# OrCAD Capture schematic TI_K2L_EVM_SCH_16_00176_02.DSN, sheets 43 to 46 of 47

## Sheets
43 PAGE10 : K2L_FMC MARCONI CONN-1: size C; title: FMC Interface to JESD/RF devices-1
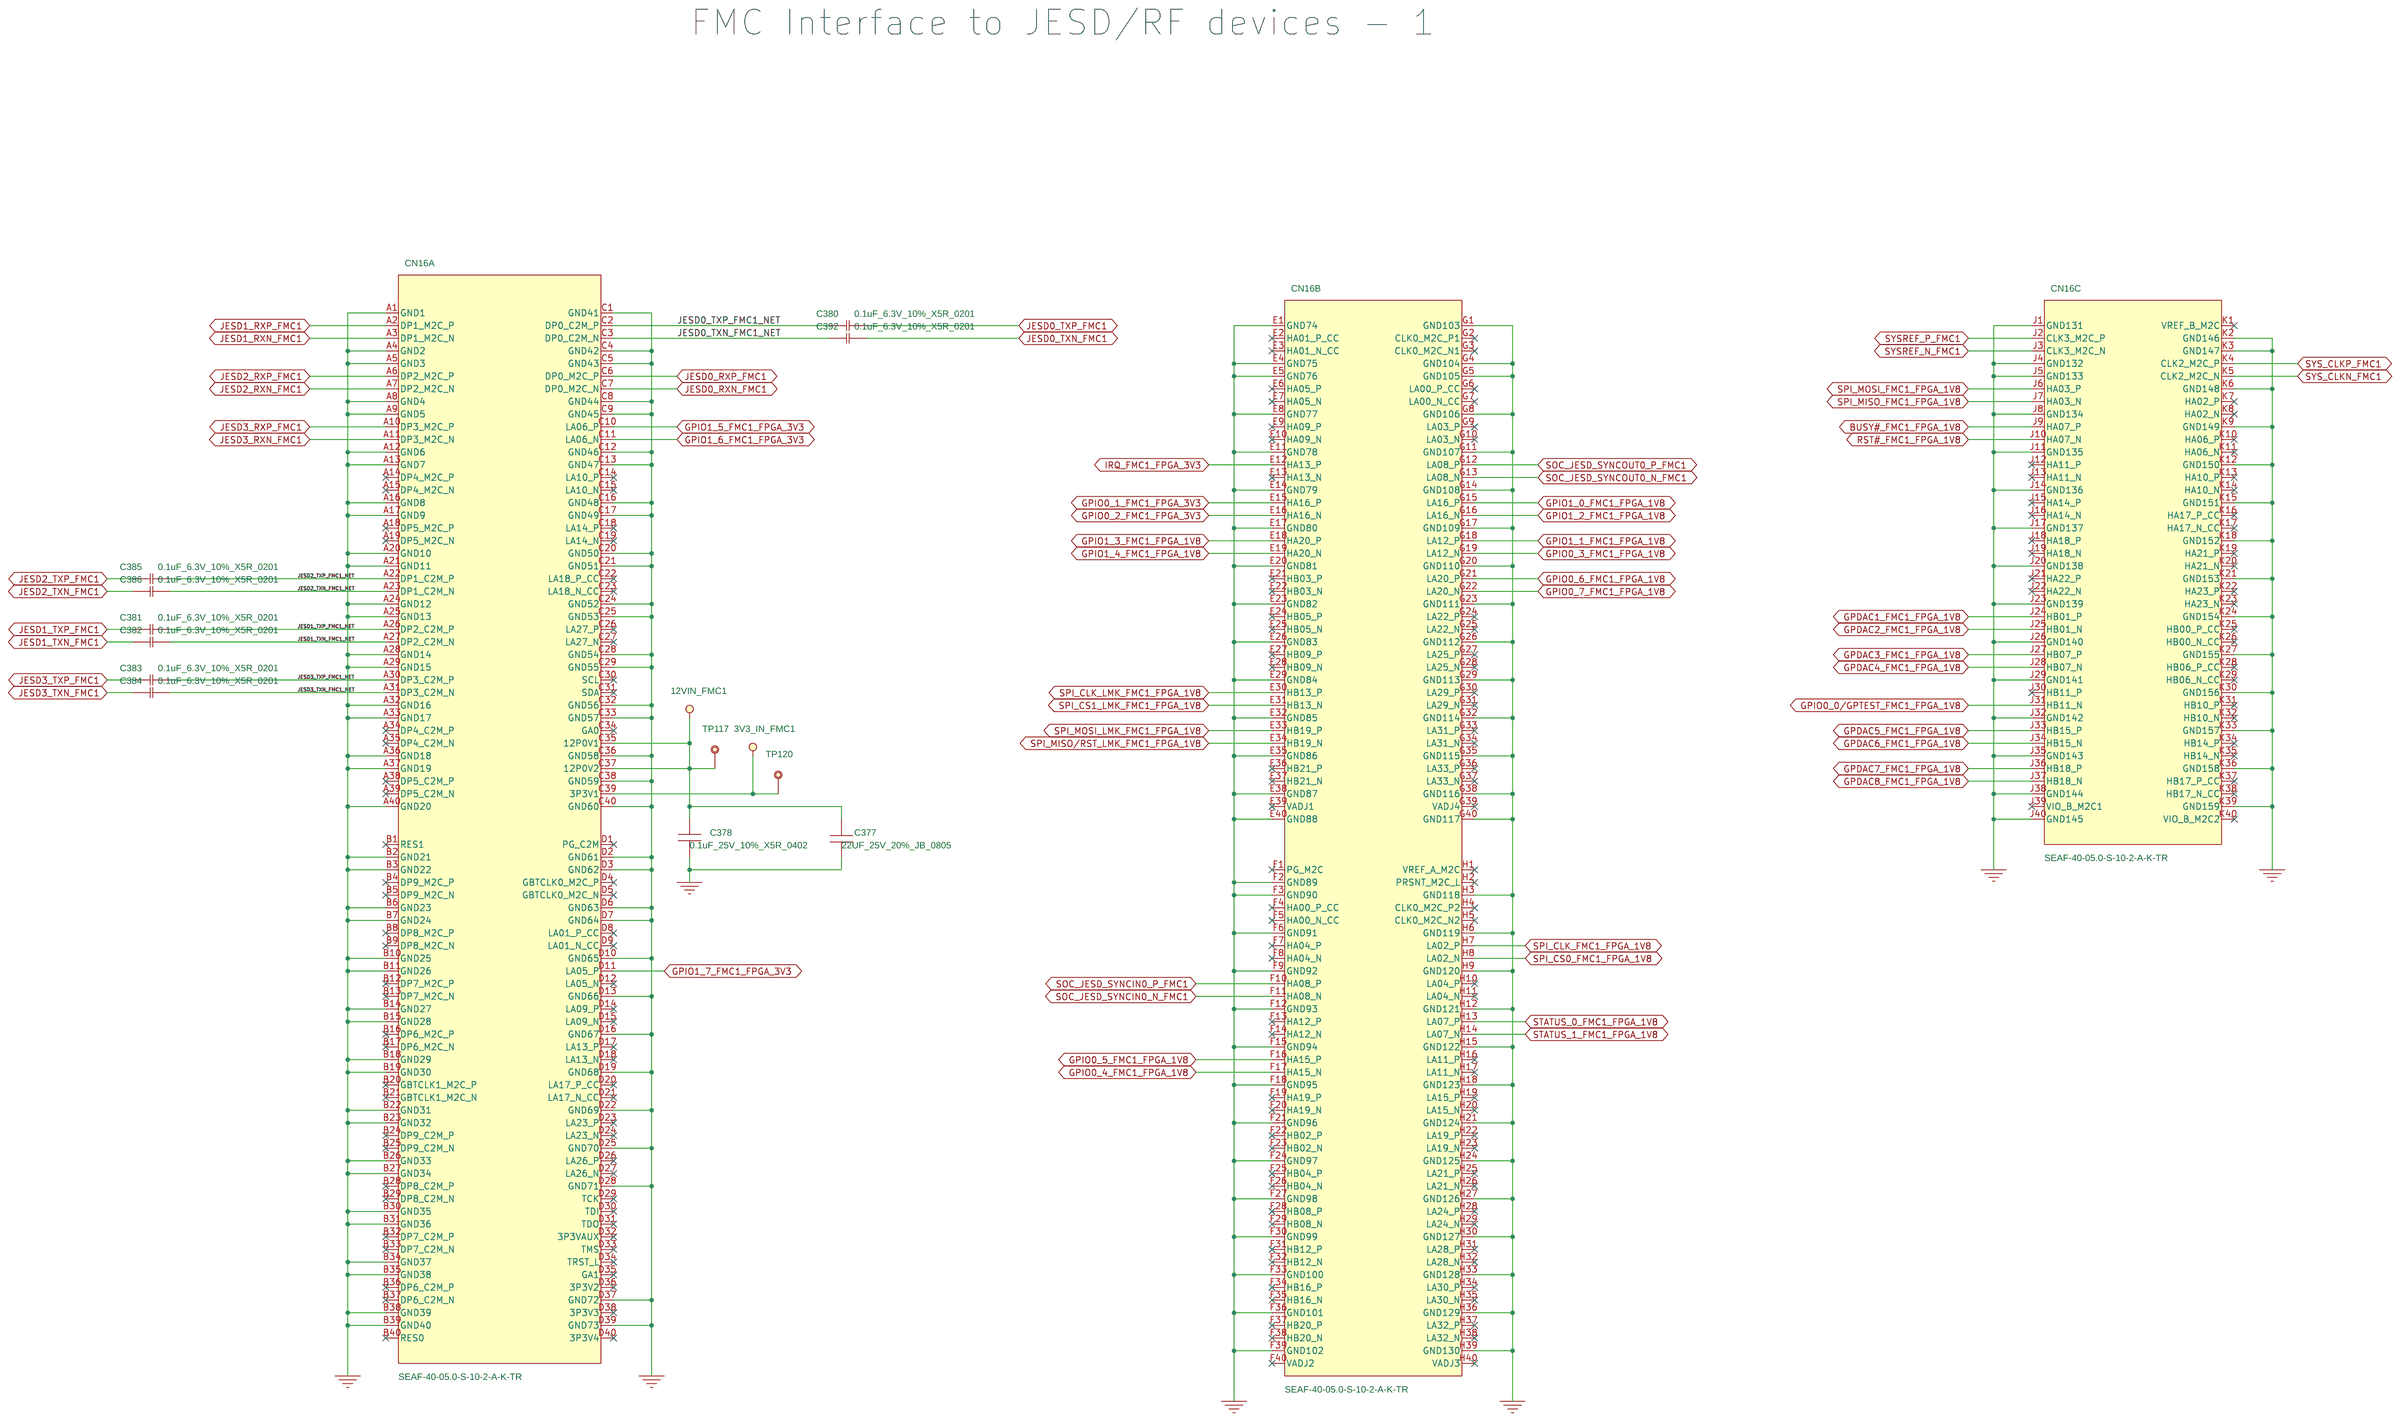
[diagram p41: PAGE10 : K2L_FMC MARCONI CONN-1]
44 PAGE03 : SYSTEM BLOCK DIAGRAM_C: title: BLOCK DIAGRAM
45 PAGE12 : K2L_SOC&FMC SERDES SW1: size C; title: JESD Serdes switch - 1
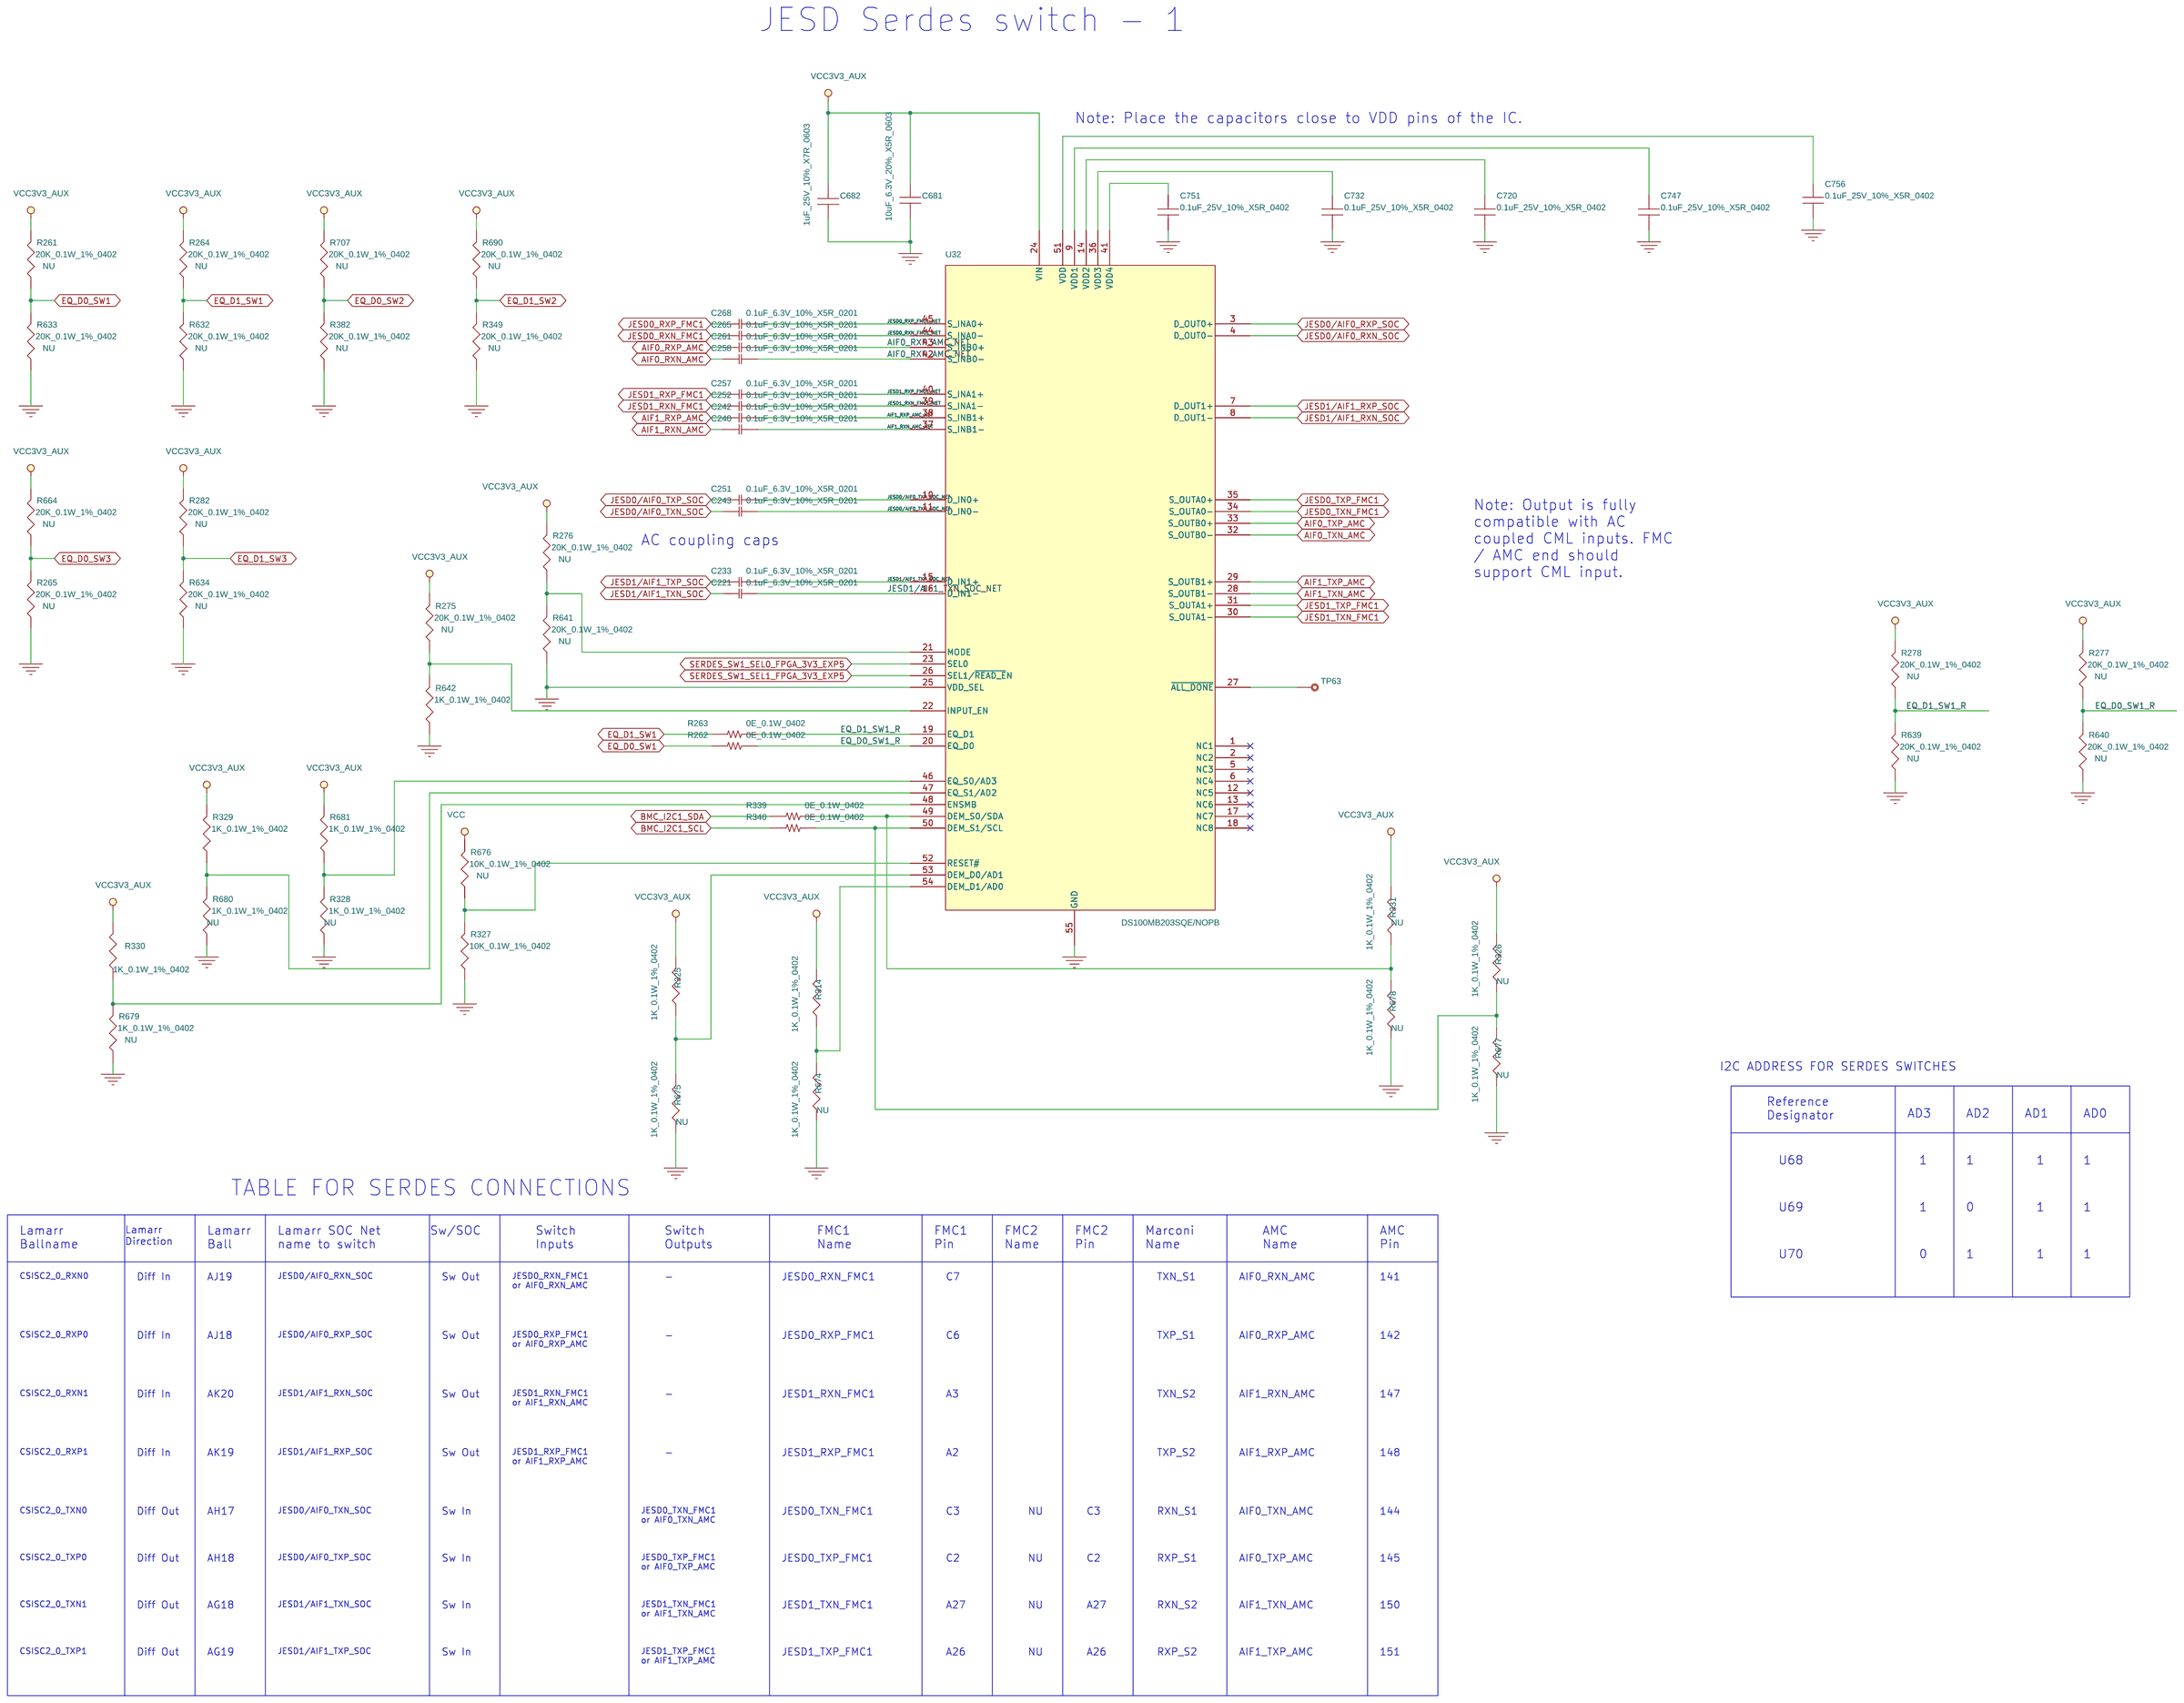
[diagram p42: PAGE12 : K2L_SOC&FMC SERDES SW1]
46 PAGE11 : K2L_FMC MARCONI CONN-2: size C; title: FMC Interface to JESD/RF devices - 2
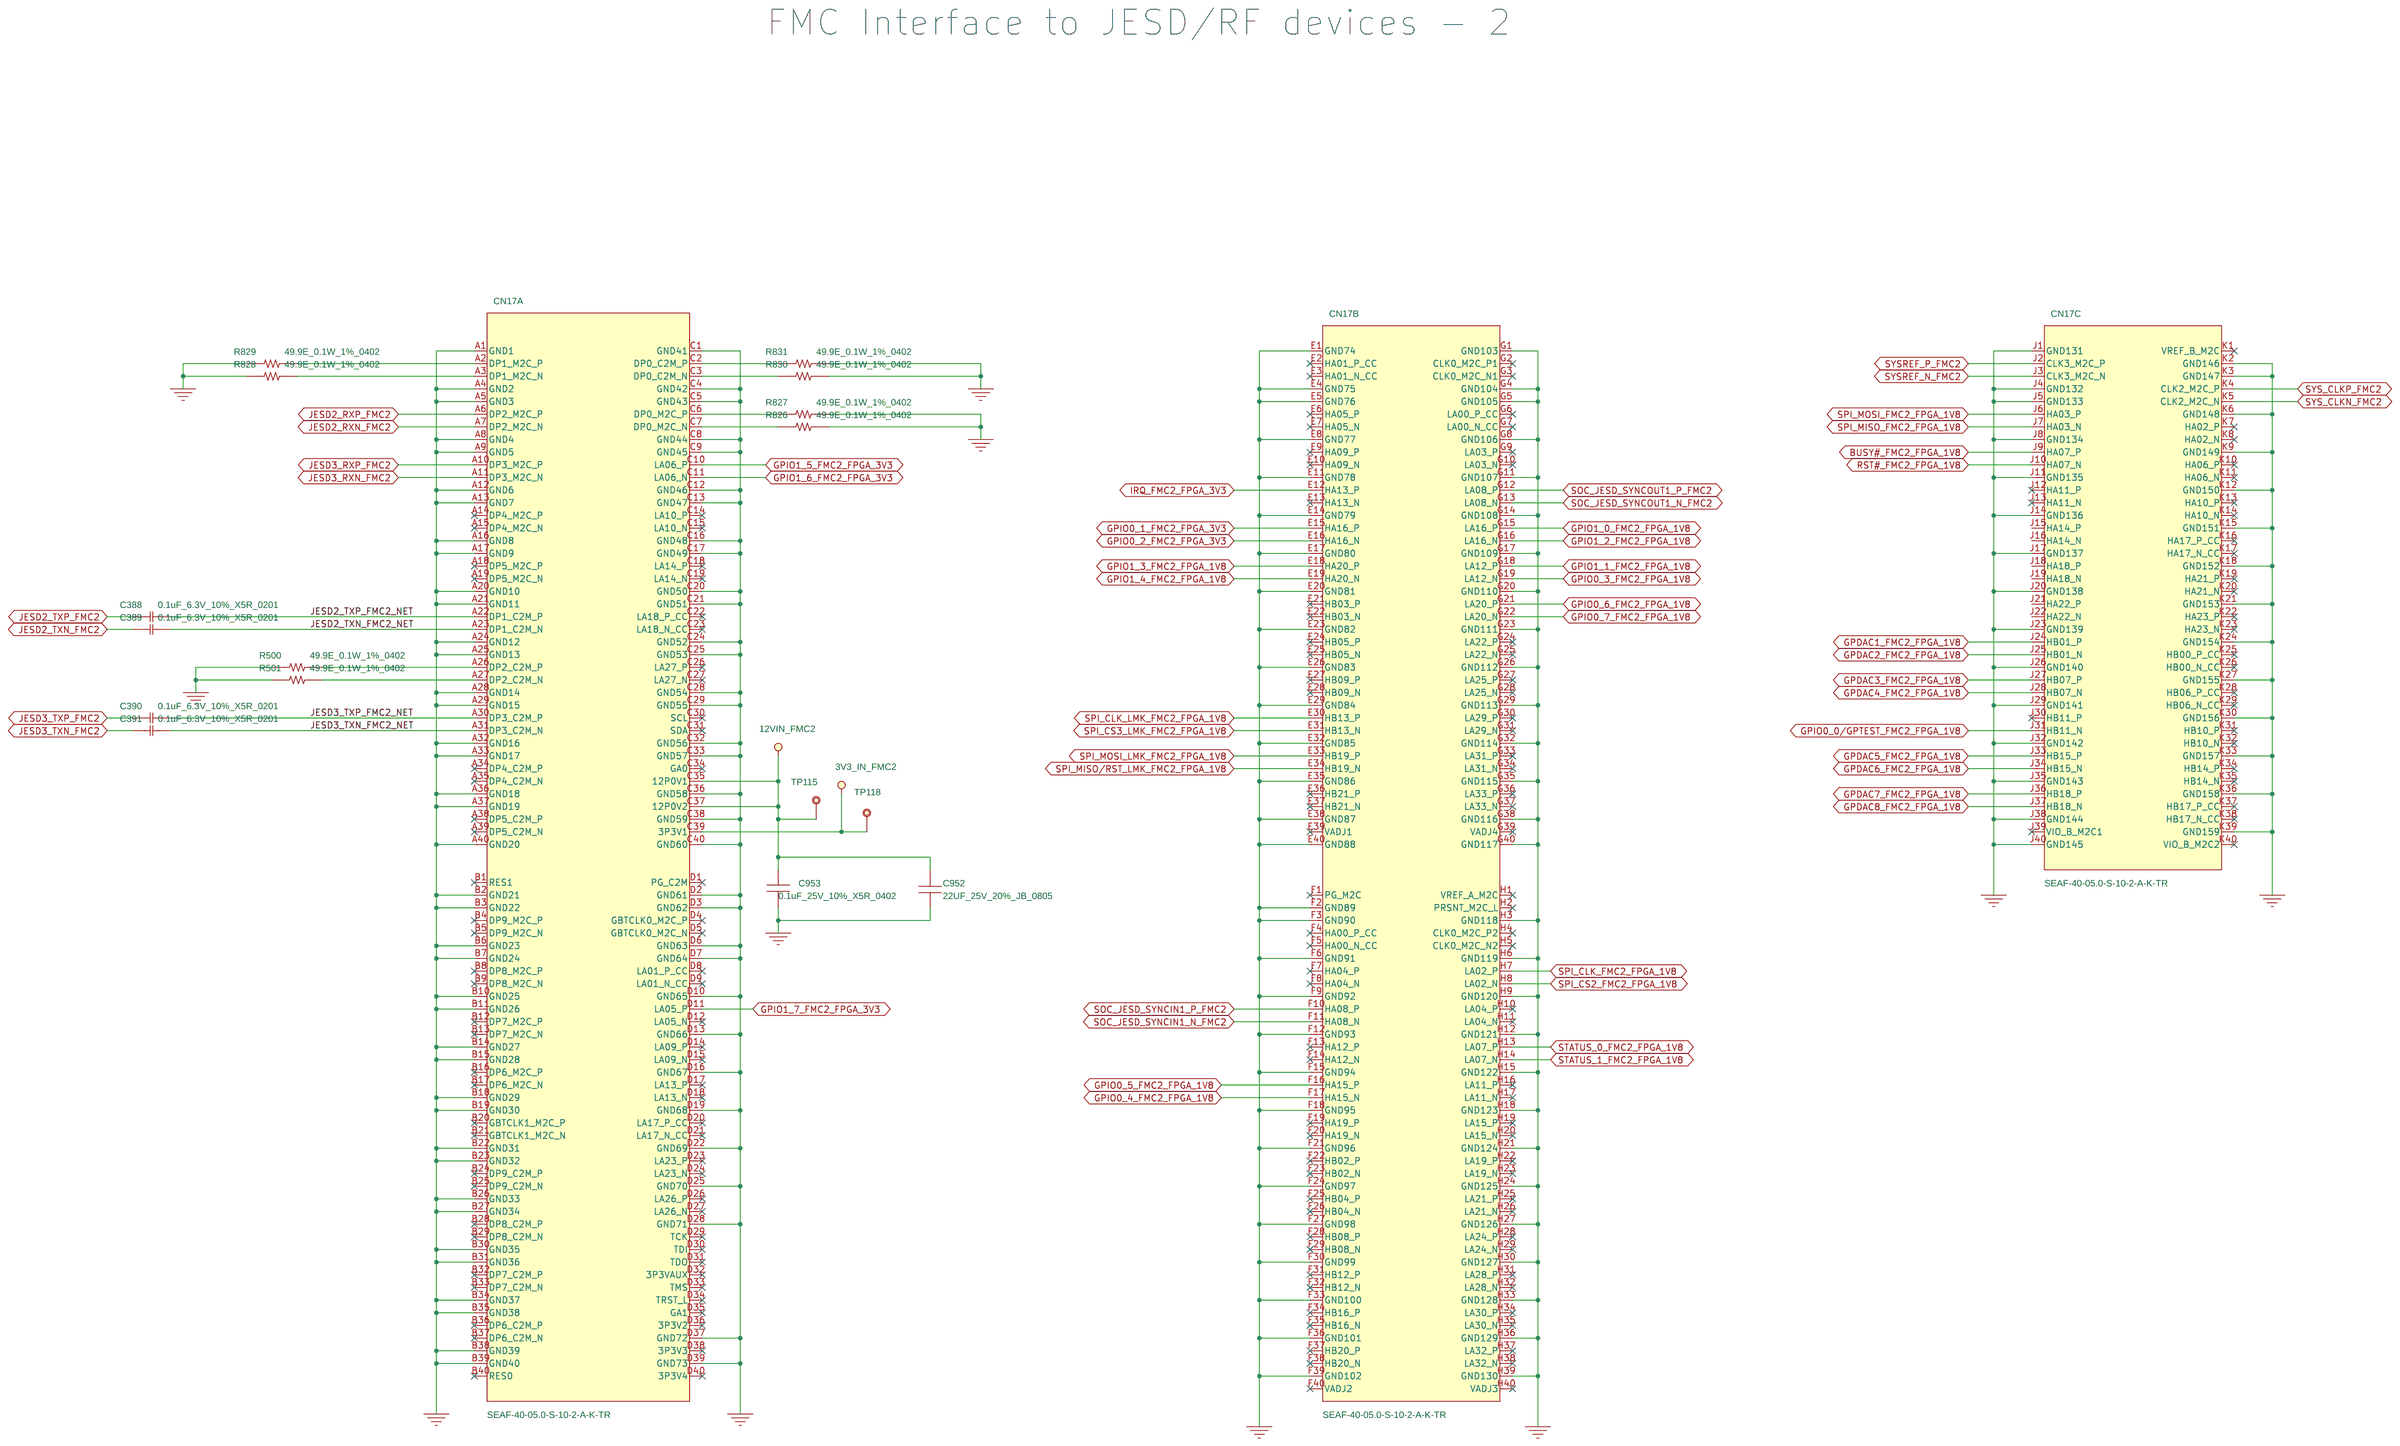
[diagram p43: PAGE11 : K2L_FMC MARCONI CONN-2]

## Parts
sheet PAGE10 : K2L_FMC MARCONI CONN-1
C377  22UF_25V_20%_JB_0805  [C0805]
C378  0.1uF_25V_10%_X5R_0402  [C0402]
C380  0.1uF_6.3V_10%_X5R_0201  [CC0201]
C381  0.1uF_6.3V_10%_X5R_0201  [CC0201]
C382  0.1uF_6.3V_10%_X5R_0201  [CC0201]
C383  0.1uF_6.3V_10%_X5R_0201  [CC0201]
C384  0.1uF_6.3V_10%_X5R_0201  [CC0201]
C385  0.1uF_6.3V_10%_X5R_0201  [CC0201]
C386  0.1uF_6.3V_10%_X5R_0201  [CC0201]
C392  0.1uF_6.3V_10%_X5R_0201  [CC0201]
CN16  SEAF-40-05.0-S-10-2-A-K-TR  [SAMTEC_SEAF4005P0S102AKTR]  (sections A,B,C)
TP117  TP  [TP-S40]
TP120  TP  [TP-S40]
sheet PAGE11 : K2L_FMC MARCONI CONN-2
C388  0.1uF_6.3V_10%_X5R_0201  [CC0201]
C389  0.1uF_6.3V_10%_X5R_0201  [CC0201]
C390  0.1uF_6.3V_10%_X5R_0201  [CC0201]
C391  0.1uF_6.3V_10%_X5R_0201  [CC0201]
C952  22UF_25V_20%_JB_0805  [C0805]
C953  0.1uF_25V_10%_X5R_0402  [C0402]
CN17  SEAF-40-05.0-S-10-2-A-K-TR  [SAMTEC_SEAF4005P0S102AKTR]  (sections A,B,C)
R500  49.9E_0.1W_1%_0402  [R0402]
R501  49.9E_0.1W_1%_0402  [R0402]
R826  49.9E_0.1W_1%_0402  [R0402]
R827  49.9E_0.1W_1%_0402  [R0402]
R828  49.9E_0.1W_1%_0402  [R0402]
R829  49.9E_0.1W_1%_0402  [R0402]
R830  49.9E_0.1W_1%_0402  [R0402]
R831  49.9E_0.1W_1%_0402  [R0402]
TP115  TP  [TP-S40]
TP118  TP  [TP-S40]
sheet PAGE12 : K2L_SOC&FMC SERDES SW1
C221  0.1uF_6.3V_10%_X5R_0201  [CC0201]
C233  0.1uF_6.3V_10%_X5R_0201  [CC0201]
C240  0.1uF_6.3V_10%_X5R_0201  [CC0201]
C242  0.1uF_6.3V_10%_X5R_0201  [CC0201]
C243  0.1uF_6.3V_10%_X5R_0201  [CC0201]
C251  0.1uF_6.3V_10%_X5R_0201  [CC0201]
C252  0.1uF_6.3V_10%_X5R_0201  [CC0201]
C257  0.1uF_6.3V_10%_X5R_0201  [CC0201]
C258  0.1uF_6.3V_10%_X5R_0201  [CC0201]
C261  0.1uF_6.3V_10%_X5R_0201  [CC0201]
C265  0.1uF_6.3V_10%_X5R_0201  [CC0201]
C268  0.1uF_6.3V_10%_X5R_0201  [CC0201]
C681  10uF_6.3V_20%_X5R_0603  [C0603]
C682  1uF_25V_10%_X7R_0603  [C0603]
C720  0.1uF_25V_10%_X5R_0402  [C0402]
C732  0.1uF_25V_10%_X5R_0402  [C0402]
C747  0.1uF_25V_10%_X5R_0402  [C0402]
C751  0.1uF_25V_10%_X5R_0402  [C0402]
C756  0.1uF_25V_10%_X5R_0402  [C0402]
R261  20K_0.1W_1%_0402  [RC0402]
R262  0E_0.1W_0402  [R0402]
R263  0E_0.1W_0402  [R0402]
R264  20K_0.1W_1%_0402  [RC0402]
R265  20K_0.1W_1%_0402  [RC0402]
R275  20K_0.1W_1%_0402  [RC0402]
R276  20K_0.1W_1%_0402  [RC0402]
R277  20K_0.1W_1%_0402  [RC0402]
R278  20K_0.1W_1%_0402  [RC0402]
R282  20K_0.1W_1%_0402  [RC0402]
R314  1K_0.1W_1%_0402  [R0402]
R325  1K_0.1W_1%_0402  [R0402]
R326  1K_0.1W_1%_0402  [R0402]
R327  10K_0.1W_1%_0402  [R0402]
R328  1K_0.1W_1%_0402  [R0402]
R329  1K_0.1W_1%_0402  [R0402]
R330  1K_0.1W_1%_0402  [R0402]
R331  1K_0.1W_1%_0402  [R0402]
R339  0E_0.1W_0402  [R0402]
R340  0E_0.1W_0402  [R0402]
R349  20K_0.1W_1%_0402  [RC0402]
R382  20K_0.1W_1%_0402  [RC0402]
R632  20K_0.1W_1%_0402  [RC0402]
R633  20K_0.1W_1%_0402  [RC0402]
R634  20K_0.1W_1%_0402  [RC0402]
R639  20K_0.1W_1%_0402  [RC0402]
R640  20K_0.1W_1%_0402  [RC0402]
R641  20K_0.1W_1%_0402  [RC0402]
R642  1K_0.1W_1%_0402  [R0402]
R664  20K_0.1W_1%_0402  [RC0402]
R674  1K_0.1W_1%_0402  [R0402]
R675  1K_0.1W_1%_0402  [R0402]
R676  10K_0.1W_1%_0402  [R0402]
R677  1K_0.1W_1%_0402  [R0402]
R678  1K_0.1W_1%_0402  [R0402]
R679  1K_0.1W_1%_0402  [R0402]
R680  1K_0.1W_1%_0402  [R0402]
R681  1K_0.1W_1%_0402  [R0402]
R690  20K_0.1W_1%_0402  [RC0402]
R707  20K_0.1W_1%_0402  [RC0402]
TP63  TP  [TP-S40]
U32  DS100MB203SQE/NOPB  [QFN50P550X1000X80-55N_EINF]

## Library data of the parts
C377 C952 = DISC_CAP_NP: CAP CER 22UF 25V 20% JB 0805; Alternate_Mfr: Samsung; Alternate_Partno: CL21A226MAQNNNE; Distributor_name: DIGIKEY; Distributor_part_number: 445-11475-2-ND; EIC Part#: 03_00586_01; Manufacture: TDK Corporation; Manufacture Part Number: C2012JB1E226M125AC; Manufacture(English): TDK Corporation; Manufacture_Part_Number: C2012JB1E226M125AC; Manufacturer: TDK Corporation; Manufacturer_Part_No: C2012JB1E226M125AC; Mfg: TDK Corporation; Mfg Part#: C2012JB1E226M125AC; Mfr_name: TDK Corporation; Mfr_part_number: C2012JB1E226M125AC; Package: 0805; Price @ 1: 2.04000; Price @ 10K: 0.52962; Price @ 1K: 0.61110; Vendor: DIGIKEY; Vendor Part#: 490-5527-1-ND; Vendor_Part_No: 03_00586_01; eI Part#: 03_00586_01
C378 C720 C732 C747 C751 C756 C953 = CAP: CAP CER 0.1UF 25V 10% X5R 0402; Distributor_name: DIGIKEY; Distributor_part_number: 445-4964-1-ND; EIC Part#: 03_00470_02; Manufacture: TDK Corporation; Manufacture Part Number: C1005X5R1E104K050BC; Manufacture(English): TDK Corporation; Manufacture_Part_Number: GRM155R61E104KA87D; Manufacturer: TDK Corporation; Manufacturer_Part_No: C1005X5R1E104K050BC; Mfg: Murata Electronics North America; Mfg Part#: 03_00470_02; Mfr_name: TDK Corporation; Mfr_part_number: C1005X5R1E104K050BC; Price @ 1: 0.10000; Price @ 1K: 0.00960; Vendor: DIGIKEY; Vendor Part#: 445-4964-1-ND; Vendor_Part_No: 445-4964-1-ND; eI Part#: 03_00470_02
C221 C233 C240 C242 C243 C251 C252 C257 C258 C261 C265 C268 C380-C386 C388-C392 = 11_C_12: CAP CER 0.1UF 6.3V 10% X5R 0201; Alt Mfg: Taiyo Yuden; Alt Mfg Part#: TMK105BJ104KV-F; Characteristic: <Characteristic>; Distributor_name: DIGIKEY; Distributor_part_number: 445-1796-1-ND; EIC Part#: 03_00583_01; Manufacture: TDK Corporation; Manufacture Part Number: C0603X5R0J104K030BC; Manufacture(English): TDK Corporation; Manufacture_Part_Number: C0603X5R0J104K030BC; Manufacturer: TDK Corporation; Manufacturer_Part_No: C0603X5R0J104K030BC; Mfg: TDK Corporation; Mfg Part#: 03_00583_01; Mfr_name: TDK Corporation; Mfr_part_number: C0603X5R0J104K030BC; Oper. Temp. Range: -55°C ~ 85°C; Package: 0201; Price @ 1: 0.10000; Price @ 10K: 0.00675; Price @ 1K: 0.00810; ProcessType: SMT; RoHS: Yes; Tolerance: 10%; Vendor: DIGIKEY; Vendor Part#: 445-1796-2-ND; Vendor_Part_No: 445-1796-1-ND; Voltage: 6.3V; eI Part#: 03_00583_01
CN16 = SEAF-40-05.0-S-10-2-A-K-TR: CONN SNGL-END ARRAY FMALE 400POS; Distributor_name: DIGIKEY; Distributor_part_number: SAM8009CT-ND; EIC Part#: TBD; Manufacture: Samtec Inc; Manufacture(English): Samtec Inc; Manufacturer: Samtec Inc; Mfg: Samtec; Mfg Part#: TBD; Mfr_name: Samtec Inc; Price @ 1: 30.05000; Price @ 1K: 23.51200; Vendor: DIGIKEY; Vendor_Part_No: SAM8009CT-ND; eI Part#: TBD; Location X-Coordinate: 0; Location Y-Coordinate: 0; Primitive: DEFAULT
TP115 TP117 TP120 = 00_TP28_0: TEST PAD TP; Advansus_Part_Number: 0030000003; Avalue_Part_Number: 0030000003; Distributor_name: NA; Distributor_part_number: NA; EIC Part#: NA; Manufacture: NA; Manufacture Part Number: NA; Manufacture(English): NA; Manufacture_Part_Number: NA; Manufacturer: NA; Manufacturer_Part_No: NA; Mfg: NA; Mfg Part#: NA; Mfr_name: NA; Mfr_part_number: NA; Part_Number: 0030000003; Price @ 1: NA; Price @ 10K: NA; Price @ 1K: NA; ProcessType: SMT; Vendor: NA; Vendor_Part_No: NA; eI Part#: NA
CN17 = SEAF-40-05.0-S-10-2-A-K-TR: CONN SNGL-END ARRAY FMALE 400POS; Distributor_name: DIGIKEY; Distributor_part_number: SAM8009CT-ND; EIC Part#: TBD; Manufacture: Samtec Inc; Manufacture(English): Samtec Inc; Manufacturer: Samtec Inc; Mfg: Samtec; Mfg Part#: TBD; Mfr_name: Samtec Inc; Price @ 1: 30.05000; Price @ 1K: 23.51200; Vendor: DIGIKEY; Vendor_Part_No: SAM8009CT-ND; eI Part#: TBD; Primitive: DEFAULT; SPLIT_INST: TRUE; SWAP_INFO: (S1+S2+S3)
R500 R501 R826-R831 = 10_R_0: RES 49.9 OHM 1/10W 1% 0402 SMD; Distributor_name: DIGIKEY; Distributor_part_number: P49.9LCT-ND; EIC Part#: 02_00025_01; Manufacture: Panasonic - ECG; Manufacture Part Number: ERJ-2RKF49R9X; Manufacture(English): Panasonic - ECG; Manufacture_Part_Number: ERJ-2RKF49R9X; Manufacturer: Panasonic - ECG; Manufacturer_Part_No: ERJ-2RKF49R9X; Mfg: Panasonic - ECG; Mfg Part#: ERJ-2RKF49R9X; Mfr_name: Panasonic - ECG; Mfr_part_number: ERJ-2RKF49R9X; Price @ 1: 0.10000; Price @ 10K: 0.00347; Price @ 1K: 0.00672; Vendor: DIGIKEY; Vendor Part#: P49.9LCT-ND; Vendor_Part_No: P49.9LCT-ND; eI Part#: 02_00025_01
TP118 = 00_TP28_0: TEST PAD TP; Advansus_Part_Number: 0030000003; Avalue_Part_Number: 0030000003; Distributor_name: NA; Distributor_part_number: NA; EIC Part#: NA; Manufacture: NA; Manufacture Part Number: NA; Manufacture(English): NA; Manufacture_Part_Number: NA; Manufacturer: NA; Manufacturer_Part_No: NA; Mfg: NA; Mfg Part#: NA; Mfr_name: NA; Mfr_part_number: NA; Part_Number: 0030000003; Price @ 1: NA; Price @ 10K: NA; Price @ 1K: NA; ProcessType: SMT; Vendor: NA; Vendor_Part_No: NA; eI Part#: 01_01118_01
C681 = CAP: CAP CER 10UF 6.3V 20% X5R 0603; Distributor_name: DIGIKEY; Distributor_part_number: 587-3383-1-ND; EIC Part#: 03_00605_01; Manufacture: Taiyo Yuden; Manufacture Part Number: JMK107ABJ106MAHT; Manufacture(English): Taiyo Yuden; Manufacture_Part_Number: JMK107ABJ106MAHT; Manufacturer: Taiyo Yuden; Manufacturer_Part_No: JMK107ABJ106MAHT; Mfg: Taiyo Yuden; Mfg Part#: JMK107ABJ106MAHT; Mfr_name: Taiyo Yuden; Mfr_part_number: JMK107ABJ106MAHT; Price @ 1: 0.44000; Price @ 10K: 0.06105; Price @ 1K: 0.12650; Vendor: DIGIKEY; Vendor_Part_No: 587-3383-1-ND; eI Part#: 03_00605_01
C682 = CAP: CAP CER 1UF 25V 10% X5R 0603; Distributor_name: DIGIKEY; Distributor_part_number: 490-3897-1-ND; EIC Part#: 03_00161_02; Manufacture: Murata; Manufacture Part Number: GRM188R61E105KA12D; Manufacture(English): Murata; Manufacture_Part_Number: GRM188R71E105KA12D; Manufacturer: Murata; Manufacturer_Part_No: GRM188R61E105KA12D; Mfg: Murata; Mfg Part#: 03_00161_02; Mfr_name: Murata; Mfr_part_number: GRM188R61E105KA12D; Price @ 1: 0.38000; Price @ 10K: 0.07363; Price @ 1K: 0.09353; Vendor: DIGIKEY; Vendor_Part_No: 490-3897-1-ND; eI Part#: 03_00161_02
R261 R264 R349 R632 R633 = DISC_RESISTOR: RES 20.0K OHM 1/10W 1% 0402 SMD; Distributor_name: DIGIKEY; Distributor_part_number: P20.0KLCT-ND; EIC Part#: 02_00037_01; Manufacture: Panasonic - ECG; Manufacture Part Number: ERJ-2RKF2002X; Manufacture(English): Panasonic - ECG; Manufacture_Part_Number: ERJ-2RKF2002X; Manufacturer: Panasonic - ECG; Manufacturer_Part_No: ERJ-2RKF2002X; Mfg Part#: 02_00037_01; Mfr_name: Panasonic - ECG; Mfr_part_number: ERJ-2RKF2002X; Mounting Status: NU; Mounting_Status: NU; Price @ 1: 0.10000; Price @ 10K: 0.00347; Price @ 1K: 0.00672; Vendor: DIGIKEY; Vendor_Part_No: P20.0KLCT-ND; eI Part#: 02_00037_01
R262 R263 R339 R340 = 10_R_0: RES 0.0 OHM 1/10W JUMP 0402 SMD; Distributor_name: DIGIKEY; Distributor_part_number: P0.0JCT-ND; EIC Part#: 02_00019_01; Manufacture: Panasonic - ECG; Manufacture Part Number: ERJ-2GE0R00X; Manufacture(English): Panasonic - ECG; Manufacture_Part_Number: ERJ-2GE0R00X; Manufacturer: Panasonic - ECG; Manufacturer_Part_No: ERJ-2GE0R00X; Mfg: PANASONIC ELECTRONIC COMPONENTS (VA); Mfg Part#: 02_00019_01; Mfr_name: Panasonic - ECG; Mfr_part_number: ERJ-2GE0R00X; Price @ 1: 0.05000; Price @ 10K: 0.00248; Price @ 1K: 0.00480; Vendor: DIGIKEY; Vendor_Part_No: P0.0JCT-ND; eI Part#: 02_00019_01
R265 R275 R382 R634 R664 R707 = DISC_RESISTOR: RES 20.0K OHM 1/10W 1% 0402 SMD; Distributor_name: DIGIKEY; Distributor_part_number: P20.0KLCT-ND; EIC Part#: 02_00037_01; Manufacture: Panasonic - ECG; Manufacture Part Number: ERJ-2RKF2002X; Manufacture(English): Panasonic - ECG; Manufacture_Part_Number: ERJ-2RKF2002X; Manufacturer: Panasonic - ECG; Manufacturer_Part_No: ERJ-2RKF2002X; Mfg Part#: 02_00037_01; Mfr_name: Panasonic - ECG; Mfr_part_number: ERJ-2RKF2002X; Mounting Status: NU; Mounting_Status: NU; Price @ 1: 0.10000; Price @ 10K: 0.00347; Price @ 1K: 0.00672; Vendor: DIGIKEY; Vendor_Part_No: P20.0KLCT-ND; eI Part#: 02_00045_01
R276 R641 = DISC_RESISTOR: RES 20.0K OHM 1/10W 1% 0402 SMD; Distributor_name: DIGIKEY; Distributor_part_number: P20.0KLCT-ND; EIC Part#: 02_00037_01; Manufacture: Panasonic - ECG; Manufacture Part Number: ERJ-2RKF2002X; Manufacture(English): Panasonic - ECG; Manufacture_Part_Number: ERJ-2RKF2002X; Manufacturer: Panasonic - ECG; Manufacturer_Part_No: ERJ-2RKF2002X; Mfg Part#: 02_00037_01; Mfr_name: Panasonic - ECG; Mfr_part_number: ERJ-2RKF2002X; Mounting Status: NU; Mounting_Status: NU; Price @ 1: 0.10000; Price @ 10K: 0.00347; Price @ 1K: 0.00672; Vendor: DIGIKEY; Vendor_Part_No: P20.0KLCT-ND; eI Part#: 02_00348_01
R277 R690 = DISC_RESISTOR: RES 20.0K OHM 1/10W 1% 0402 SMD; Distributor_name: DIGIKEY; Distributor_part_number: P20.0KLCT-ND; EIC Part#: 02_00037_01; Manufacture: Panasonic - ECG; Manufacture Part Number: ERJ-2RKF2002X; Manufacture(English): Panasonic - ECG; Manufacture_Part_Number: ERJ-2RKF2002X; Manufacturer: Panasonic - ECG; Manufacturer_Part_No: ERJ-2RKF2002X; Mfg Part#: 02_00037_01; Mfr_name: Panasonic - ECG; Mfr_part_number: ERJ-2RKF2002X; Mounting Status: NU; Mounting_Status: NU; Price @ 1: 0.10000; Price @ 10K: 0.00347; Price @ 1K: 0.00672; Vendor: DIGIKEY; Vendor_Part_No: P20.0KLCT-ND; eI Part#: 02_00019_01
R278 R640 = DISC_RESISTOR: RES 20.0K OHM 1/10W 1% 0402 SMD; Distributor_name: DIGIKEY; Distributor_part_number: P20.0KLCT-ND; EIC Part#: 02_00037_01; Manufacture: Panasonic - ECG; Manufacture Part Number: ERJ-2RKF2002X; Manufacture(English): Panasonic - ECG; Manufacture_Part_Number: ERJ-2RKF2002X; Manufacturer: Panasonic - ECG; Manufacturer_Part_No: ERJ-2RKF2002X; Mfg Part#: 02_00037_01; Mfr_name: Panasonic - ECG; Mfr_part_number: ERJ-2RKF2002X; Mounting Status: NU; Mounting_Status: NU; Price @ 1: 0.10000; Price @ 10K: 0.00347; Price @ 1K: 0.00672; Vendor: DIGIKEY; Vendor_Part_No: P20.0KLCT-ND; eI Part#: 02_00967_01
R282 = DISC_RESISTOR: RES 20.0K OHM 1/10W 1% 0402 SMD; Distributor_name: DIGIKEY; Distributor_part_number: P20.0KLCT-ND; EIC Part#: 02_00037_01; Manufacture: Panasonic - ECG; Manufacture Part Number: ERJ-2RKF2002X; Manufacture(English): Panasonic - ECG; Manufacture_Part_Number: ERJ-2RKF2002X; Manufacturer: Panasonic - ECG; Manufacturer_Part_No: ERJ-2RKF2002X; Mfg Part#: 02_00037_01; Mfr_name: Panasonic - ECG; Mfr_part_number: ERJ-2RKF2002X; Mounting Status: NU; Mounting_Status: NU; Price @ 1: 0.10000; Price @ 10K: 0.00347; Price @ 1K: 0.00672; Vendor: DIGIKEY; Vendor_Part_No: P20.0KLCT-ND; eI Part#: 02_00027_01
R314 R325 = RESISTOR: RES 1.00K OHM 1/10W 1% 0402 SMD; Distributor_name: DIGIKEY; Distributor_part_number: P1.00KLCT-ND; EI Part#: 02_00045_01; EIC Part#: 02_00045_01; Manufacture: Panasonic - ECG; Manufacture Part Number: ERJ-2RKF1001X; Manufacture(English): Panasonic - ECG; Manufacture_Part_Number: ERJ-2RKF1001X; Manufacturer: Panasonic - ECG; Manufacturer_Part_No: ERJ-2RKF1001X; Mfg Part#: 02_00045_01; Mfr_name: Panasonic - ECG; Mfr_part_number: ERJ-2RKF1001X; Price @ 1: 0.10000; Price @ 10K: 0.00347; Price @ 1K: 0.00672; Vendor: DIGIKEY; Vendor_Part_No: P1.00KLCT-ND
R326 R331 R674 R675 R677 R678 = RESISTOR: RES 1.00K OHM 1/10W 1% 0402 SMD; Distributor_name: DIGIKEY; Distributor_part_number: P1.00KLCT-ND; EI Part#: 02_00045_01; EIC Part#: 02_00045_01; Manufacture: Panasonic - ECG; Manufacture Part Number: ERJ-2RKF1001X; Manufacture(English): Panasonic - ECG; Manufacture_Part_Number: ERJ-2RKF1001X; Manufacturer: Panasonic - ECG; Manufacturer_Part_No: ERJ-2RKF1001X; Mfg Part#: 02_00045_01; Mfr_name: Panasonic - ECG; Mfr_part_number: ERJ-2RKF1001X; Mounting Status: NU; Mounting_Status: NU; Price @ 1: 0.10000; Price @ 10K: 0.00347; Price @ 1K: 0.00672; Vendor: DIGIKEY; Vendor_Part_No: P1.00KLCT-ND
R327 = DISC_RESISTOR: RES 10K OHM 1/10W 1% 0402 SMD; Distributor_name: DIGIKEY; Distributor_part_number: P10.0KLCT-ND; EIC Part#: 02_00027_01; Manufacture: Panasonic - ECG; Manufacture Part Number: ERJ-2RKF1002X; Manufacture(English): Panasonic - ECG; Manufacture_Part_Number: ERJ-2RKF1002X; Manufacturer: Panasonic - ECG; Manufacturer_Part_No: ERJ-2RKF1002X; Mfg Part#: 02_00027_01; Mfr_name: Panasonic - ECG; Mfr_part_number: ERJ-2RKF1002X; Package: 0402; Price @ 1: 0.10000; Price @ 10K: 0.00347; Price @ 1K: 0.00672; Vendor: DIGIKEY; Vendor_Part_No: P10.0KLCT-ND; eI Part#: 02_00027_01
R328 R679 R680 = DISC_RESISTOR: RES 1.00K OHM 1/10W 1% 0402 SMD; Distributor_name: DIGIKEY; Distributor_part_number: P1.00KLCT-ND; EIC Part#: 02_00045_01; Manufacture: Panasonic - ECG; Manufacture Part Number: ERJ-2RKF1001X; Manufacture(English): Panasonic - ECG; Manufacture_Part_Number: ERJ-2RKF1001X; Manufacturer: Panasonic - ECG; Manufacturer_Part_No: ERJ-2RKF1001X; Mfg Part#: 02_00045_01; Mfr_name: Panasonic - ECG; Mfr_part_number: ERJ-2RKF1001X; Mounting Status: NU; Mounting_Status: NU; Price @ 1: 0.10000; Price @ 10K: 0.00347; Price @ 1K: 0.00672; Vendor: DIGIKEY; Vendor_Part_No: P1.00KLCT-ND; eI Part#: 02_00045_01
R329 R330 R642 R681 = DISC_RESISTOR: RES 1.00K OHM 1/10W 1% 0402 SMD; Distributor_name: DIGIKEY; Distributor_part_number: P1.00KLCT-ND; EIC Part#: 02_00045_01; Manufacture: Panasonic - ECG; Manufacture Part Number: ERJ-2RKF1001X; Manufacture(English): Panasonic - ECG; Manufacture_Part_Number: ERJ-2RKF1001X; Manufacturer: Panasonic - ECG; Manufacturer_Part_No: ERJ-2RKF1001X; Mfg Part#: 02_00045_01; Mfr_name: Panasonic - ECG; Mfr_part_number: ERJ-2RKF1001X; Price @ 1: 0.10000; Price @ 10K: 0.00347; Price @ 1K: 0.00672; Vendor: DIGIKEY; Vendor_Part_No: P1.00KLCT-ND; eI Part#: 02_00045_01
R639 = DISC_RESISTOR: RES 20.0K OHM 1/10W 1% 0402 SMD; Distributor_name: DIGIKEY; Distributor_part_number: P20.0KLCT-ND; EIC Part#: 02_00037_01; Manufacture: Panasonic - ECG; Manufacture Part Number: ERJ-2RKF2002X; Manufacture(English): Panasonic - ECG; Manufacture_Part_Number: ERJ-2RKF2002X; Manufacturer: Panasonic - ECG; Manufacturer_Part_No: ERJ-2RKF2002X; Mfg Part#: 02_00037_01; Mfr_name: Panasonic - ECG; Mfr_part_number: ERJ-2RKF2002X; Mounting Status: NU; Mounting_Status: NU; Price @ 1: 0.10000; Price @ 10K: 0.00347; Price @ 1K: 0.00672; Vendor: DIGIKEY; Vendor_Part_No: P20.0KLCT-ND; eI Part#: 02_00061_02
R676 = DISC_RESISTOR: RES 10K OHM 1/10W 1% 0402 SMD; Distributor_name: DIGIKEY; Distributor_part_number: P10.0KLCT-ND; EIC Part#: 02_00027_01; Manufacture: Panasonic - ECG; Manufacture Part Number: ERJ-2RKF1002X; Manufacture(English): Panasonic - ECG; Manufacture_Part_Number: ERJ-2RKF1002X; Manufacturer: Panasonic - ECG; Manufacturer_Part_No: ERJ-2RKF1002X; Mfg Part#: 02_00027_01; Mfr_name: Panasonic - ECG; Mfr_part_number: ERJ-2RKF1002X; Mounting: NU; Mounting Status: NU; Mounting_Status: NU; Package: 0402; Price @ 1: 0.10000; Price @ 10K: 0.00347; Price @ 1K: 0.00672; Vendor: DIGIKEY; Vendor_Part_No: P10.0KLCT-ND; eI Part#: 02_00027_01
TP63 = 00_TP-S40_0: TEST PAD TP; Distributor_name: NA; Distributor_part_number: NA; EIC Part#: NA; Manufacture: NA; Manufacture Part Number: NA; Manufacture(English): NA; Manufacture_Part_Number: NA; Manufacturer: NA; Manufacturer_Part_No: NA; Mfg: NA; Mfg Part#: NA; Mfr_name: NA; Mfr_part_number: NA; Oper. Temp. Range: --NA--; Package: --NA--; Price @ 1: NA; Price @ 10K: NA; Price @ 1K: NA; ProcessType: SMT; RoHS: Yes; Vendor: NA; Vendor Part#: --NA--; Vendor_Part_No: NA; eI Part#: NA
U32 = DS100MB203SQE: IC MUX/BUFFER DUAL PORT 54WQF; Distributor_name: DIGIKEY; Distributor_part_number: DS100MB203SQE/NOPB-ND; EIC Part#: TBD; Manufacture: TI; Manufacture(English): TI; Manufacturer: TI; Mfg: TI; Mfg Part#: TBD; Mfr_name: TI; Price @ 10K: 14.33300; Price @ 1K: 14.33300; Vendor: DIGIKEY; Vendor_Part_No: DS100MB203SQE/NOPB-ND; eI Part#: 01_01133_01

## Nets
3V3_IN_FMC1: CN16.C39(3P3V1) TP120.1 ; also on sheet 25
3V3_IN_FMC2: CN17.C39(3P3V1) TP118.1 ; also on sheet 25
12VIN_FMC1: C377.2 C378.1 CN16.C35(12P0V1) CN16.C37(12P0V2) TP117.1 ; also on sheet 25
12VIN_FMC2: C952.2 C953.1 CN17.C35(12P0V1) CN17.C37(12P0V2) TP115.1 ; also on sheet 25
GND: C377.1 C378.2 C681.2 C682.1 C720.2 C732.2 C747.2 C751.2 C756.2 C952.1 C953.2 CN16.A1(GND1) CN16.A4(GND2) CN16.A5(GND3) CN16.A8(GND4) CN16.A9(GND5) CN16.A12(GND6) CN16.A13(GND7) CN16.A16(GND8) CN16.A17(GND9) CN16.A20(GND10) CN16.A21(GND11) CN16.A24(GND12) CN16.A25(GND13) CN16.A28(GND14) CN16.A29(GND15) CN16.A32(GND16) CN16.A33(GND17) CN16.A36(GND18) CN16.A37(GND19) CN16.A40(GND20) CN16.B2(GND21) CN16.B3(GND22) CN16.B6(GND23) CN16.B7(GND24) CN16.B10(GND25) CN16.B11(GND26) CN16.B14(GND27) CN16.B15(GND28) CN16.B18(GND29) CN16.B19(GND30) CN16.B22(GND31) CN16.B23(GND32) CN16.B26(GND33) CN16.B27(GND34) CN16.B30(GND35) CN16.B31(GND36) CN16.B34(GND37) CN16.B35(GND38) CN16.B38(GND39) CN16.B39(GND40) CN16.C1(GND41) CN16.C4(GND42) CN16.C5(GND43) CN16.C8(GND44) CN16.C9(GND45) CN16.C12(GND46) CN16.C13(GND47) CN16.C16(GND48) CN16.C17(GND49) CN16.C20(GND50) CN16.C21(GND51) CN16.C24(GND52) CN16.C25(GND53) CN16.C28(GND54) CN16.C29(GND55) CN16.C32(GND56) CN16.C33(GND57) CN16.C36(GND58) CN16.C38(GND59) CN16.C40(GND60) CN16.D2(GND61) CN16.D3(GND62) CN16.D6(GND63) CN16.D7(GND64) CN16.D10(GND65) CN16.D13(GND66) CN16.D16(GND67) CN16.D19(GND68) CN16.D22(GND69) CN16.D25(GND70) CN16.D28(GND71) CN16.D37(GND72) CN16.D39(GND73) CN16.E1(GND74) CN16.E4(GND75) CN16.E5(GND76) CN16.E8(GND77) CN16.E11(GND78) CN16.E14(GND79) CN16.E17(GND80) CN16.E20(GND81) CN16.E23(GND82) CN16.E26(GND83) CN16.E29(GND84) CN16.E32(GND85) CN16.E35(GND86) CN16.E38(GND87) CN16.E40(GND88) CN16.F2(GND89) CN16.F3(GND90) CN16.F6(GND91) CN16.F9(GND92) CN16.F12(GND93) CN16.F15(GND94) CN16.F18(GND95) CN16.F21(GND96) CN16.F24(GND97) CN16.F27(GND98) CN16.F30(GND99) CN16.F33(GND100) CN16.F36(GND101) CN16.F39(GND102) CN16.G1(GND103) CN16.G4(GND104) CN16.G5(GND105) CN16.G8(GND106) CN16.G11(GND107) CN16.G14(GND108) CN16.G17(GND109) CN16.G20(GND110) CN16.G23(GND111) CN16.G26(GND112) CN16.G29(GND113) CN16.G32(GND114) CN16.G35(GND115) CN16.G38(GND116) CN16.G40(GND117) CN16.H3(GND118) CN16.H6(GND119) CN16.H9(GND120) CN16.H12(GND121) CN16.H15(GND122) CN16.H18(GND123) CN16.H21(GND124) CN16.H24(GND125) CN16.H27(GND126) CN16.H30(GND127) CN16.H33(GND128) CN16.H36(GND129) CN16.H39(GND130) CN16.J1(GND131) CN16.J4(GND132) CN16.J5(GND133) CN16.J8(GND134) CN16.J11(GND135) CN16.J14(GND136) CN16.J17(GND137) CN16.J20(GND138) CN16.J23(GND139) CN16.J26(GND140) CN16.J29(GND141) CN16.J32(GND142) CN16.J35(GND143) CN16.J38(GND144) CN16.J40(GND145) CN16.K2(GND146) CN16.K3(GND147) CN16.K6(GND148) CN16.K9(GND149) CN16.K12(GND150) CN16.K15(GND151) CN16.K18(GND152) CN16.K21(GND153) CN16.K24(GND154) CN16.K27(GND155) CN16.K30(GND156) CN16.K33(GND157) CN16.K36(GND158) CN16.K39(GND159) CN17.A1(GND1) CN17.A4(GND2) CN17.A5(GND3) CN17.A8(GND4) CN17.A9(GND5) CN17.A12(GND6) CN17.A13(GND7) CN17.A16(GND8) CN17.A17(GND9) CN17.A20(GND10) CN17.A21(GND11) CN17.A24(GND12) CN17.A25(GND13) CN17.A28(GND14) CN17.A29(GND15) CN17.A32(GND16) CN17.A33(GND17) CN17.A36(GND18) CN17.A37(GND19) CN17.A40(GND20) CN17.B2(GND21) CN17.B3(GND22) CN17.B6(GND23) CN17.B7(GND24) CN17.B10(GND25) CN17.B11(GND26) CN17.B14(GND27) CN17.B15(GND28) CN17.B18(GND29) CN17.B19(GND30) CN17.B22(GND31) CN17.B23(GND32) CN17.B26(GND33) CN17.B27(GND34) CN17.B30(GND35) CN17.B31(GND36) CN17.B34(GND37) CN17.B35(GND38) CN17.B38(GND39) CN17.B39(GND40) CN17.C1(GND41) CN17.C4(GND42) CN17.C5(GND43) CN17.C8(GND44) CN17.C9(GND45) CN17.C12(GND46) CN17.C13(GND47) CN17.C16(GND48) CN17.C17(GND49) CN17.C20(GND50) CN17.C21(GND51) CN17.C24(GND52) CN17.C25(GND53) CN17.C28(GND54) CN17.C29(GND55) CN17.C32(GND56) CN17.C33(GND57) CN17.C36(GND58) CN17.C38(GND59) CN17.C40(GND60) CN17.D2(GND61) CN17.D3(GND62) CN17.D6(GND63) CN17.D7(GND64) CN17.D10(GND65) CN17.D13(GND66) CN17.D16(GND67) CN17.D19(GND68) CN17.D22(GND69) CN17.D25(GND70) CN17.D28(GND71) CN17.D37(GND72) CN17.D39(GND73) CN17.E1(GND74) CN17.E4(GND75) CN17.E5(GND76) CN17.E8(GND77) CN17.E11(GND78) CN17.E14(GND79) CN17.E17(GND80) CN17.E20(GND81) CN17.E23(GND82) CN17.E26(GND83) CN17.E29(GND84) CN17.E32(GND85) CN17.E35(GND86) CN17.E38(GND87) CN17.E40(GND88) CN17.F2(GND89) CN17.F3(GND90) CN17.F6(GND91) CN17.F9(GND92) CN17.F12(GND93) CN17.F15(GND94) CN17.F18(GND95) CN17.F21(GND96) CN17.F24(GND97) CN17.F27(GND98) CN17.F30(GND99) CN17.F33(GND100) CN17.F36(GND101) CN17.F39(GND102) CN17.G1(GND103) CN17.G4(GND104) CN17.G5(GND105) CN17.G8(GND106) CN17.G11(GND107) CN17.G14(GND108) CN17.G17(GND109) CN17.G20(GND110) CN17.G23(GND111) CN17.G26(GND112) CN17.G29(GND113) CN17.G32(GND114) CN17.G35(GND115) CN17.G38(GND116) CN17.G40(GND117) CN17.H3(GND118) CN17.H6(GND119) CN17.H9(GND120) CN17.H12(GND121) CN17.H15(GND122) CN17.H18(GND123) CN17.H21(GND124) CN17.H24(GND125) CN17.H27(GND126) CN17.H30(GND127) CN17.H33(GND128) CN17.H36(GND129) CN17.H39(GND130) CN17.J1(GND131) CN17.J4(GND132) CN17.J5(GND133) CN17.J8(GND134) CN17.J11(GND135) CN17.J14(GND136) CN17.J17(GND137) CN17.J20(GND138) CN17.J23(GND139) CN17.J26(GND140) CN17.J29(GND141) CN17.J32(GND142) CN17.J35(GND143) CN17.J38(GND144) CN17.J40(GND145) CN17.K2(GND146) CN17.K3(GND147) CN17.K6(GND148) CN17.K9(GND149) CN17.K12(GND150) CN17.K15(GND151) CN17.K18(GND152) CN17.K21(GND153) CN17.K24(GND154) CN17.K27(GND155) CN17.K30(GND156) CN17.K33(GND157) CN17.K36(GND158) CN17.K39(GND159) R265.1 R327.1 R328.1 R349.1 R382.1 R500.1 R501.1 R632.1 R633.1 R634.1 R639.1 R640.1 R641.1 R642.1 R674.2 R675.2 R677.2 R678.2 R679.1 R680.1 R826.2 R827.2 R828.1 R829.1 R830.2 R831.2 U32.25(VDD_SEL) U32.55(GND) ; also on sheet 1 2 3 4 5 6 8 10 11 12 13 14 15 16 17 18 19 20 21 22 24 25 26 27 28 29 33 34 35 36 37 40 41 42 47
VCC3V3_AUX: C681.1 C682.2 R261.2 R264.2 R275.2 R276.2 R277.2 R278.2 R282.2 R314.1 R325.1 R326.1 R329.2 R330.2 R331.1 R664.2 R676.2 R681.2 R690.2 R707.2 U32.24(VIN) ; also on sheet 2 4 6 8 11 12 13 16 18 19 22 25 26 27 28 29 33 35 37 40 47
AIF0_RXN_AMC: C258.1 ; also on sheet 18
AIF0_RXN_AMC_NET: C258.2 U32.42(S_INB0-)
AIF0_RXP_AMC: C261.1 ; also on sheet 18
AIF0_RXP_AMC_NET: C261.2 U32.43(S_INB0+)
AIF0_TXN_AMC: U32.32(S_OUTB0-) ; also on sheet 18
AIF0_TXP_AMC: U32.33(S_OUTB0+) ; also on sheet 18
AIF1_RXN_AMC: C240.1 ; also on sheet 18
AIF1_RXN_AMC_NET: C240.2 U32.37(S_INB1-)
AIF1_RXP_AMC: C242.1 ; also on sheet 18
AIF1_RXP_AMC_NET: C242.2 U32.38(S_INB1+)
AIF1_TXN_AMC: U32.28(S_OUTB1-) ; also on sheet 18
AIF1_TXP_AMC: U32.29(S_OUTB1+) ; also on sheet 18
BMC_I2C1_SCL: R340.1 ; also on sheet 4 5 40 41 47
BMC_I2C1_SDA: R339.1 ; also on sheet 4 5 40 41 47
BUSY#_FMC1_FPGA_1V8: CN16.J9(HA07_P) ; also on sheet 27
BUSY#_FMC2_FPGA_1V8: CN17.J9(HA07_P) ; also on sheet 27
EQ_D0_SW1: R261.1 R262.1 R633.2
EQ_D0_SW1_R: R262.2 R277.1 R640.2 U32.20(EQ_D0)
EQ_D0_SW2: R382.2 R707.1 ; also on sheet 47
EQ_D0_SW3: R265.2 R664.1 ; also on sheet 40
EQ_D1_SW1: R263.1 R264.1 R632.2
EQ_D1_SW1_R: R263.2 R278.1 R639.2 U32.19(EQ_D1)
EQ_D1_SW2: R349.2 R690.1 ; also on sheet 47
EQ_D1_SW3: R282.1 R634.2 ; also on sheet 40
GPDAC1_FMC1_FPGA_1V8: CN16.J24(HB01_P) ; also on sheet 27
GPDAC1_FMC2_FPGA_1V8: CN17.J24(HB01_P) ; also on sheet 27
GPDAC2_FMC1_FPGA_1V8: CN16.J25(HB01_N) ; also on sheet 27
GPDAC2_FMC2_FPGA_1V8: CN17.J25(HB01_N) ; also on sheet 27
GPDAC3_FMC1_FPGA_1V8: CN16.J27(HB07_P) ; also on sheet 27
GPDAC3_FMC2_FPGA_1V8: CN17.J27(HB07_P) ; also on sheet 27
GPDAC4_FMC1_FPGA_1V8: CN16.J28(HB07_N) ; also on sheet 27
GPDAC4_FMC2_FPGA_1V8: CN17.J28(HB07_N) ; also on sheet 27
GPDAC5_FMC1_FPGA_1V8: CN16.J33(HB15_P) ; also on sheet 27
GPDAC5_FMC2_FPGA_1V8: CN17.J33(HB15_P) ; also on sheet 27
GPDAC6_FMC1_FPGA_1V8: CN16.J34(HB15_N) ; also on sheet 27
GPDAC6_FMC2_FPGA_1V8: CN17.J34(HB15_N) ; also on sheet 27
GPDAC7_FMC1_FPGA_1V8: CN16.J36(HB18_P) ; also on sheet 27
GPDAC7_FMC2_FPGA_1V8: CN17.J36(HB18_P) ; also on sheet 27
GPDAC8_FMC1_FPGA_1V8: CN16.J37(HB18_N) ; also on sheet 27
GPDAC8_FMC2_FPGA_1V8: CN17.J37(HB18_N) ; also on sheet 27
GPIO0_0/GPTEST_FMC1_FPGA_1V8: CN16.J31(HB11_N) ; also on sheet 27
GPIO0_0/GPTEST_FMC2_FPGA_1V8: CN17.J31(HB11_N) ; also on sheet 27
GPIO0_1_FMC1_FPGA_3V3: CN16.E15(HA16_P) ; also on sheet 27
GPIO0_1_FMC2_FPGA_3V3: CN17.E15(HA16_P) ; also on sheet 27
GPIO0_2_FMC1_FPGA_3V3: CN16.E16(HA16_N) ; also on sheet 27
GPIO0_2_FMC2_FPGA_3V3: CN17.E16(HA16_N) ; also on sheet 27
GPIO0_3_FMC1_FPGA_1V8: CN16.G19(LA12_N) ; also on sheet 27
GPIO0_3_FMC2_FPGA_1V8: CN17.G19(LA12_N) ; also on sheet 27
GPIO0_4_FMC1_FPGA_1V8: CN16.F17(HA15_N) ; also on sheet 27
GPIO0_4_FMC2_FPGA_1V8: CN17.F17(HA15_N) ; also on sheet 27
GPIO0_5_FMC1_FPGA_1V8: CN16.F16(HA15_P) ; also on sheet 27
GPIO0_5_FMC2_FPGA_1V8: CN17.F16(HA15_P) ; also on sheet 27
GPIO0_6_FMC1_FPGA_1V8: CN16.G21(LA20_P) ; also on sheet 27
GPIO0_6_FMC2_FPGA_1V8: CN17.G21(LA20_P) ; also on sheet 27
GPIO0_7_FMC1_FPGA_1V8: CN16.G22(LA20_N) ; also on sheet 27
GPIO0_7_FMC2_FPGA_1V8: CN17.G22(LA20_N) ; also on sheet 27
GPIO1_0_FMC1_FPGA_1V8: CN16.G15(LA16_P) ; also on sheet 27
GPIO1_0_FMC2_FPGA_1V8: CN17.G15(LA16_P) ; also on sheet 27
GPIO1_1_FMC1_FPGA_1V8: CN16.G18(LA12_P) ; also on sheet 27
GPIO1_1_FMC2_FPGA_1V8: CN17.G18(LA12_P) ; also on sheet 27
GPIO1_2_FMC1_FPGA_1V8: CN16.G16(LA16_N) ; also on sheet 27
GPIO1_2_FMC2_FPGA_1V8: CN17.G16(LA16_N) ; also on sheet 27
GPIO1_3_FMC1_FPGA_1V8: CN16.E18(HA20_P) ; also on sheet 27
GPIO1_3_FMC2_FPGA_1V8: CN17.E18(HA20_P) ; also on sheet 27
GPIO1_4_FMC1_FPGA_1V8: CN16.E19(HA20_N) ; also on sheet 27
GPIO1_4_FMC2_FPGA_1V8: CN17.E19(HA20_N) ; also on sheet 27
GPIO1_5_FMC1_FPGA_3V3: CN16.C10(LA06_P) ; also on sheet 27
GPIO1_5_FMC2_FPGA_3V3: CN17.C10(LA06_P) ; also on sheet 27
GPIO1_6_FMC1_FPGA_3V3: CN16.C11(LA06_N) ; also on sheet 27
GPIO1_6_FMC2_FPGA_3V3: CN17.C11(LA06_N) ; also on sheet 27
GPIO1_7_FMC1_FPGA_3V3: CN16.D11(LA05_P) ; also on sheet 27
GPIO1_7_FMC2_FPGA_3V3: CN17.D11(LA05_P) ; also on sheet 27
IRQ_FMC1_FPGA_3V3: CN16.E12(HA13_P) ; also on sheet 27
IRQ_FMC2_FPGA_3V3: CN17.E12(HA13_P) ; also on sheet 27
JESD0/AIF0_RXN_SOC: U32.4(D_OUT0-) ; also on sheet 16
JESD0/AIF0_RXP_SOC: U32.3(D_OUT0+) ; also on sheet 16
JESD0/AIF0_TXN_SOC: C243.1 ; also on sheet 16
JESD0/AIF0_TXN_SOC_NET: C243.2 U32.11(D_IN0-)
JESD0/AIF0_TXP_SOC: C251.1 ; also on sheet 16
JESD0/AIF0_TXP_SOC_NET: C251.2 U32.10(D_IN0+)
JESD0_RXN_FMC1: C265.1 CN16.C7(DP0_M2C_N)
JESD0_RXN_FMC1_NET: C265.2 U32.44(S_INA0-)
JESD0_RXP_FMC1: C268.1 CN16.C6(DP0_M2C_P)
JESD0_RXP_FMC1_NET: C268.2 U32.45(S_INA0+)
JESD0_TXN_FMC1: C392.2 U32.34(S_OUTA0-)
JESD0_TXN_FMC1_NET: C392.1 CN16.C3(DP0_C2M_N)
JESD0_TXP_FMC1: C380.2 U32.35(S_OUTA0+)
JESD0_TXP_FMC1_NET: C380.1 CN16.C2(DP0_C2M_P)
JESD1/AIF1_RXN_SOC: U32.8(D_OUT1-) ; also on sheet 16
JESD1/AIF1_RXP_SOC: U32.7(D_OUT1+) ; also on sheet 16
JESD1/AIF1_TXN_SOC: C221.1 ; also on sheet 16
JESD1/AIF1_TXN_SOC_NET: C221.2 U32.16(D_IN1-)
JESD1/AIF1_TXP_SOC: C233.1 ; also on sheet 16
JESD1/AIF1_TXP_SOC_NET: C233.2 U32.15(D_IN1+)
JESD1_RXN_FMC1: C252.1 CN16.A3(DP1_M2C_N)
JESD1_RXN_FMC1_NET: C252.2 U32.39(S_INA1-)
JESD1_RXP_FMC1: C257.1 CN16.A2(DP1_M2C_P)
JESD1_RXP_FMC1_NET: C257.2 U32.40(S_INA1+)
JESD1_TXN_FMC1: C382.1 U32.30(S_OUTA1-)
JESD1_TXN_FMC1_NET: C382.2 CN16.A27(DP2_C2M_N)
JESD1_TXP_FMC1: C381.1 U32.31(S_OUTA1+)
JESD1_TXP_FMC1_NET: C381.2 CN16.A26(DP2_C2M_P)
JESD2_RXN_FMC1: CN16.A7(DP2_M2C_N) ; also on sheet 47
JESD2_RXN_FMC2: CN17.A7(DP2_M2C_N) ; also on sheet 47
JESD2_RXP_FMC1: CN16.A6(DP2_M2C_P) ; also on sheet 47
JESD2_RXP_FMC2: CN17.A6(DP2_M2C_P) ; also on sheet 47
JESD2_TXN_FMC1: C386.1 ; also on sheet 47
JESD2_TXN_FMC1_NET: C386.2 CN16.A23(DP1_C2M_N)
JESD2_TXN_FMC2: C389.1 ; also on sheet 47
JESD2_TXN_FMC2_NET: C389.2 CN17.A23(DP1_C2M_N)
JESD2_TXP_FMC1: C385.1 ; also on sheet 47
JESD2_TXP_FMC1_NET: C385.2 CN16.A22(DP1_C2M_P)
JESD2_TXP_FMC2: C388.1 ; also on sheet 47
JESD2_TXP_FMC2_NET: C388.2 CN17.A22(DP1_C2M_P)
JESD3_RXN_FMC1: CN16.A11(DP3_M2C_N) ; also on sheet 47
JESD3_RXN_FMC2: CN17.A11(DP3_M2C_N) ; also on sheet 47
JESD3_RXP_FMC1: CN16.A10(DP3_M2C_P) ; also on sheet 47
JESD3_RXP_FMC2: CN17.A10(DP3_M2C_P) ; also on sheet 47
JESD3_TXN_FMC1: C384.1 ; also on sheet 47
JESD3_TXN_FMC1_NET: C384.2 CN16.A31(DP3_C2M_N)
JESD3_TXN_FMC2: C391.1 ; also on sheet 47
JESD3_TXN_FMC2_NET: C391.2 CN17.A31(DP3_C2M_N)
JESD3_TXP_FMC1: C383.1 ; also on sheet 47
JESD3_TXP_FMC1_NET: C383.2 CN16.A30(DP3_C2M_P)
JESD3_TXP_FMC2: C390.1 ; also on sheet 47
JESD3_TXP_FMC2_NET: C390.2 CN17.A30(DP3_C2M_P)
RST#_FMC1_FPGA_1V8: CN16.J10(HA07_N) ; also on sheet 27
RST#_FMC2_FPGA_1V8: CN17.J10(HA07_N) ; also on sheet 27
SERDES_SW1_SEL0_FPGA_3V3_EXP5: U32.23(SEL0) ; also on sheet 27
SERDES_SW1_SEL1_FPGA_3V3_EXP5: U32.26(SEL1/~{READ_E}N) ; also on sheet 27
SOC_JESD_SYNCIN0_N_FMC1: CN16.F11(HA08_N) ; also on sheet 16
SOC_JESD_SYNCIN0_P_FMC1: CN16.F10(HA08_P) ; also on sheet 16
SOC_JESD_SYNCIN1_N_FMC2: CN17.F11(HA08_N) ; also on sheet 16
SOC_JESD_SYNCIN1_P_FMC2: CN17.F10(HA08_P) ; also on sheet 16
SOC_JESD_SYNCOUT0_N_FMC1: CN16.G13(LA08_N) ; also on sheet 16
SOC_JESD_SYNCOUT0_P_FMC1: CN16.G12(LA08_P) ; also on sheet 16
SOC_JESD_SYNCOUT1_N_FMC2: CN17.G13(LA08_N) ; also on sheet 16
SOC_JESD_SYNCOUT1_P_FMC2: CN17.G12(LA08_P) ; also on sheet 16
SPI_CLK_FMC1_FPGA_1V8: CN16.H7(LA02_P) ; also on sheet 27
SPI_CLK_FMC2_FPGA_1V8: CN17.H7(LA02_P) ; also on sheet 27
SPI_CLK_LMK_FMC1_FPGA_1V8: CN16.E30(HB13_P) ; also on sheet 27
SPI_CLK_LMK_FMC2_FPGA_1V8: CN17.E30(HB13_P) ; also on sheet 27
SPI_CS0_FMC1_FPGA_1V8: CN16.H8(LA02_N) ; also on sheet 27
SPI_CS1_LMK_FMC1_FPGA_1V8: CN16.E31(HB13_N) ; also on sheet 27
SPI_CS2_FMC2_FPGA_1V8: CN17.H8(LA02_N) ; also on sheet 27
SPI_CS3_LMK_FMC2_FPGA_1V8: CN17.E31(HB13_N) ; also on sheet 27
SPI_MISO/RST_LMK_FMC1_FPGA_1V8: CN16.E34(HB19_N) ; also on sheet 27
SPI_MISO/RST_LMK_FMC2_FPGA_1V8: CN17.E34(HB19_N) ; also on sheet 27
SPI_MISO_FMC1_FPGA_1V8: CN16.J7(HA03_N) ; also on sheet 27
SPI_MISO_FMC2_FPGA_1V8: CN17.J7(HA03_N) ; also on sheet 27
SPI_MOSI_FMC1_FPGA_1V8: CN16.J6(HA03_P) ; also on sheet 27
SPI_MOSI_FMC2_FPGA_1V8: CN17.J6(HA03_P) ; also on sheet 27
SPI_MOSI_LMK_FMC1_FPGA_1V8: CN16.E33(HB19_P) ; also on sheet 27
SPI_MOSI_LMK_FMC2_FPGA_1V8: CN17.E33(HB19_P) ; also on sheet 27
STATUS_0_FMC1_FPGA_1V8: CN16.H13(LA07_P) ; also on sheet 27
STATUS_0_FMC2_FPGA_1V8: CN17.H13(LA07_P) ; also on sheet 27
STATUS_1_FMC1_FPGA_1V8: CN16.H14(LA07_N) ; also on sheet 27
STATUS_1_FMC2_FPGA_1V8: CN17.H14(LA07_N) ; also on sheet 27
SYS_CLKN_FMC1: CN16.K5(CLK2_M2C_N) ; also on sheet 11
SYS_CLKN_FMC2: CN17.K5(CLK2_M2C_N) ; also on sheet 11
SYS_CLKP_FMC1: CN16.K4(CLK2_M2C_P) ; also on sheet 11
SYS_CLKP_FMC2: CN17.K4(CLK2_M2C_P) ; also on sheet 11
SYSREF_N_FMC1: CN16.J3(CLK3_M2C_N) ; also on sheet 28
SYSREF_N_FMC2: CN17.J3(CLK3_M2C_N) ; also on sheet 28
SYSREF_P_FMC1: CN16.J2(CLK3_M2C_P) ; also on sheet 28
SYSREF_P_FMC2: CN17.J2(CLK3_M2C_P) ; also on sheet 28
N17482032: C751.1 U32.41(VDD4)
N17482041: C732.1 U32.36(VDD3)
N17482089: C720.1 U32.14(VDD2)
N17482122: C747.1 U32.9(VDD1)
N17482166: C756.1 U32.51(VDD)
N17482302: R276.1 R641.2 U32.21(MODE)
N17482678: R275.1 R642.2 U32.22(INPUT_EN)
N17482807: R330.1 R679.2 U32.48(ENSMB)
N17483761: R329.1 R680.2 U32.47(EQ_S1/AD2)
N17483871: R314.2 R674.1 U32.54(DEM_D1/AD0)
N17484044: R325.2 R675.1 U32.53(DEM_D0/AD1)
N17484251: R328.2 R681.1 U32.46(EQ_S0/AD3)
N17484640: R327.2 R676.1 U32.52(RESET#)
N19243298: CN17.A2(DP1_M2C_P) R829.2
N19243303: CN17.A3(DP1_M2C_N) R828.2
N19243699: CN17.A26(DP2_C2M_P) R500.2
N19243701: CN17.A27(DP2_C2M_N) R501.2
N19244096: CN17.C2(DP0_C2M_P) R831.1
N19244100: CN17.C3(DP0_C2M_N) R830.1
N19244890: CN17.C6(DP0_M2C_P) R827.1
N19244892: CN17.C7(DP0_M2C_N) R826.1
N19311331: TP63.1 U32.27(~{ALL_DONE})
N19608513: R326.2 R340.2 R677.1 U32.50(DEM_S1/SCL)
N19609350: R331.2 R339.2 R678.1 U32.49(DEM_S0/SDA)

Not connected (* = marked no-connect by the designer): CN16 A14(DP4_M2C_P)* A15(DP4_M2C_N)* A18(DP5_M2C_P)* A19(DP5_M2C_N)* A34(DP4_C2M_P)* A35(DP4_C2M_N)* A38(DP5_C2M_P)* A39(DP5_C2M_N)* B1(RES1)* B4(DP9_M2C_P)* B5(DP9_M2C_N)* B8(DP8_M2C_P)* B9(DP8_M2C_N)* B12(DP7_M2C_P)* B13(DP7_M2C_N)* B16(DP6_M2C_P)* B17(DP6_M2C_N)* B20(GBTCLK1_M2C_P)* B21(GBTCLK1_M2C_N)* B24(DP9_C2M_P)* B25(DP9_C2M_N)* B28(DP8_C2M_P)* B29(DP8_C2M_N)* B32(DP7_C2M_P)* B33(DP7_C2M_N)* B36(DP6_C2M_P)* B37(DP6_C2M_N)* B40(RES0)* C14(LA10_P)* C15(LA10_N)* C18(LA14_P)* C19(LA14_N)* C22(LA18_P_CC)* C23(LA18_N_CC)* C26(LA27_P)* C27(LA27_N)* C30(SCL)* C31(SDA)* C34(GA0)* D1(PG_C2M)* D4(GBTCLK0_M2C_P)* D5(GBTCLK0_M2C_N)* D8(LA01_P_CC)* D9(LA01_N_CC)* D12(LA05_N)* D14(LA09_P)* D15(LA09_N)* D17(LA13_P)* D18(LA13_N)* D20(LA17_P_CC)* D21(LA17_N_CC)* D23(LA23_P)* D24(LA23_N)* D26(LA26_P)* D27(LA26_N)* D29(TCK)* D30(TDI)* D31(TDO)* D32(3P3VAUX)* D33(TMS)* D34(TRST_L)* D35(GA1)* D36(3P3V2)* D38(3P3V3)* D40(3P3V4)* E2(HA01_P_CC)* E3(HA01_N_CC)* E6(HA05_P)* E7(HA05_N)* E9(HA09_P)* E10(HA09_N)* E13(HA13_N)* E21(HB03_P)* E22(HB03_N)* E24(HB05_P)* E25(HB05_N)* E27(HB09_P)* E28(HB09_N)* E36(HB21_P)* E37(HB21_N)* E39(VADJ1)* F1(PG_M2C)* F4(HA00_P_CC)* F5(HA00_N_CC)* F7(HA04_P)* F8(HA04_N)* F13(HA12_P)* F14(HA12_N)* F19(HA19_P)* F20(HA19_N)* F22(HB02_P)* F23(HB02_N)* F25(HB04_P)* F26(HB04_N)* F28(HB08_P)* F29(HB08_N)* F31(HB12_P)* F32(HB12_N)* F34(HB16_P)* F35(HB16_N)* F37(HB20_P)* F38(HB20_N)* F40(VADJ2)* G2(CLK0_M2C_P1)* G3(CLK0_M2C_N1)* G6(LA00_P_CC)* G7(LA00_N_CC)* G9(LA03_P)* G10(LA03_N)* G24(LA22_P)* G25(LA22_N)* G27(LA25_P)* G28(LA25_N)* G30(LA29_P)* G31(LA29_N)* G33(LA31_P)* G34(LA31_N)* G36(LA33_P)* G37(LA33_N)* G39(VADJ4)* H1(VREF_A_M2C)* H2(PRSNT_M2C_L)* H4(CLK0_M2C_P2)* H5(CLK0_M2C_N2)* H10(LA04_P)* H11(LA04_N)* H16(LA11_P)* H17(LA11_N)* H19(LA15_P)* H20(LA15_N)* H22(LA19_P)* H23(LA19_N)* H25(LA21_P)* H26(LA21_N)* H28(LA24_P)* H29(LA24_N)* H31(LA28_P)* H32(LA28_N)* H34(LA30_P)* H35(LA30_N)* H37(LA32_P)* H38(LA32_N)* H40(VADJ3)* J12(HA11_P)* J13(HA11_N)* J15(HA14_P)* J16(HA14_N)* J18(HA18_P)* J19(HA18_N)* J21(HA22_P)* J22(HA22_N)* J30(HB11_P)* J39(VIO_B_M2C1)* K1(VREF_B_M2C)* K7(HA02_P)* K8(HA02_N)* K10(HA06_P)* K11(HA06_N)* K13(HA10_P)* K14(HA10_N)* K16(HA17_P_CC)* K17(HA17_N_CC)* K19(HA21_P)* K20(HA21_N)* K22(HA23_P)* K23(HA23_N)* K25(HB00_P_CC)* K26(HB00_N_CC)* K28(HB06_P_CC)* K29(HB06_N_CC)* K31(HB10_P)* K32(HB10_N)* K34(HB14_P)* K35(HB14_N)* K37(HB17_P_CC)* K38(HB17_N_CC)* K40(VIO_B_M2C2)*; CN17 A14(DP4_M2C_P)* A15(DP4_M2C_N)* A18(DP5_M2C_P)* A19(DP5_M2C_N)* A34(DP4_C2M_P)* A35(DP4_C2M_N)* A38(DP5_C2M_P)* A39(DP5_C2M_N)* B1(RES1)* B4(DP9_M2C_P)* B5(DP9_M2C_N)* B8(DP8_M2C_P)* B9(DP8_M2C_N)* B12(DP7_M2C_P)* B13(DP7_M2C_N)* B16(DP6_M2C_P)* B17(DP6_M2C_N)* B20(GBTCLK1_M2C_P)* B21(GBTCLK1_M2C_N)* B24(DP9_C2M_P)* B25(DP9_C2M_N)* B28(DP8_C2M_P)* B29(DP8_C2M_N)* B32(DP7_C2M_P)* B33(DP7_C2M_N)* B36(DP6_C2M_P)* B37(DP6_C2M_N)* B40(RES0)* C14(LA10_P)* C15(LA10_N)* C18(LA14_P)* C19(LA14_N)* C22(LA18_P_CC)* C23(LA18_N_CC)* C26(LA27_P)* C27(LA27_N)* C30(SCL)* C31(SDA)* C34(GA0)* D1(PG_C2M)* D4(GBTCLK0_M2C_P)* D5(GBTCLK0_M2C_N)* D8(LA01_P_CC)* D9(LA01_N_CC)* D12(LA05_N)* D14(LA09_P)* D15(LA09_N)* D17(LA13_P)* D18(LA13_N)* D20(LA17_P_CC)* D21(LA17_N_CC)* D23(LA23_P)* D24(LA23_N)* D26(LA26_P)* D27(LA26_N)* D29(TCK)* D30(TDI)* D31(TDO)* D32(3P3VAUX)* D33(TMS)* D34(TRST_L)* D35(GA1)* D36(3P3V2)* D38(3P3V3)* D40(3P3V4)* E2(HA01_P_CC)* E3(HA01_N_CC)* E6(HA05_P)* E7(HA05_N)* E9(HA09_P)* E10(HA09_N)* E13(HA13_N)* E21(HB03_P)* E22(HB03_N)* E24(HB05_P)* E25(HB05_N)* E27(HB09_P)* E28(HB09_N)* E36(HB21_P)* E37(HB21_N)* E39(VADJ1)* F1(PG_M2C)* F4(HA00_P_CC)* F5(HA00_N_CC)* F7(HA04_P)* F8(HA04_N)* F13(HA12_P)* F14(HA12_N)* F19(HA19_P)* F20(HA19_N)* F22(HB02_P)* F23(HB02_N)* F25(HB04_P)* F26(HB04_N)* F28(HB08_P)* F29(HB08_N)* F31(HB12_P)* F32(HB12_N)* F34(HB16_P)* F35(HB16_N)* F37(HB20_P)* F38(HB20_N)* F40(VADJ2)* G2(CLK0_M2C_P1)* G3(CLK0_M2C_N1)* G6(LA00_P_CC)* G7(LA00_N_CC)* G9(LA03_P)* G10(LA03_N)* G24(LA22_P)* G25(LA22_N)* G27(LA25_P)* G28(LA25_N)* G30(LA29_P)* G31(LA29_N)* G33(LA31_P)* G34(LA31_N)* G36(LA33_P)* G37(LA33_N)* G39(VADJ4)* H1(VREF_A_M2C)* H2(PRSNT_M2C_L)* H4(CLK0_M2C_P2)* H5(CLK0_M2C_N2)* H10(LA04_P)* H11(LA04_N)* H16(LA11_P)* H17(LA11_N)* H19(LA15_P)* H20(LA15_N)* H22(LA19_P)* H23(LA19_N)* H25(LA21_P)* H26(LA21_N)* H28(LA24_P)* H29(LA24_N)* H31(LA28_P)* H32(LA28_N)* H34(LA30_P)* H35(LA30_N)* H37(LA32_P)* H38(LA32_N)* H40(VADJ3)* J12(HA11_P)* J13(HA11_N)* J15(HA14_P) J16(HA14_N) J18(HA18_P) J19(HA18_N) J21(HA22_P) J22(HA22_N) J30(HB11_P)* J39(VIO_B_M2C1)* K1(VREF_B_M2C)* K7(HA02_P)* K8(HA02_N)* K10(HA06_P)* K11(HA06_N)* K13(HA10_P)* K14(HA10_N)* K16(HA17_P_CC)* K17(HA17_N_CC)* K19(HA21_P)* K20(HA21_N)* K22(HA23_P)* K23(HA23_N)* K25(HB00_P_CC)* K26(HB00_N_CC)* K28(HB06_P_CC)* K29(HB06_N_CC)* K31(HB10_P)* K32(HB10_N)* K34(HB14_P)* K35(HB14_N)* K37(HB17_P_CC)* K38(HB17_N_CC)* K40(VIO_B_M2C2)*; U32 1(NC1)* 2(NC2)* 5(NC3)* 6(NC4)* 12(NC5)* 13(NC6)* 17(NC7)* 18(NC8)*

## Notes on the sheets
sheet 43
- FMC Interface to JESD/RF devices - 1
sheet 45
- JESD Serdes switch - 1
- Note: Place the capacitors close to VDD pins of the IC.
- Note: Output is fully
  compatible with AC
  coupled CML inputs. FMC
  / AMC end should
  support CML input.
- AC coupling caps
- I2C ADDRESS FOR SERDES SWITCHES
- Reference
  Designator
- AD3
- AD2
- AD1
- AD0
- U68
- 1
- 1
- 1
- 1
- TABLE FOR SERDES CONNECTIONS
- U69
- 1
- 0
- 1
- 1
- Lamarr
  Ballname
- Lamarr
  Direction
- Lamarr
  Ball
- Lamarr SOC Net
  name to switch
- Sw/SOC
- Switch
  Inputs
- Switch
  Outputs
- FMC1
  Name
- FMC1
  Pin
- FMC2
  Name
- FMC2
  Pin
- Marconi
  Name
- AMC
  Name
- AMC
  Pin
- U70
- 0
- 1
- 1
- 1
- CSISC2_0_RXN0
- Diff In
- AJ19
- JESD0/AIF0_RXN_SOC
- Sw Out
- JESD0_RXN_FMC1
  or AIF0_RXN_AMC
- -
- JESD0_RXN_FMC1
- C7
- TXN_S1
- AIF0_RXN_AMC
- 141
- CSISC2_0_RXP0
- Diff In
- AJ18
- JESD0/AIF0_RXP_SOC
- Sw Out
- JESD0_RXP_FMC1
  or AIF0_RXP_AMC
- -
- JESD0_RXP_FMC1
- C6
- TXP_S1
- AIF0_RXP_AMC
- 142
- CSISC2_0_RXN1
- Diff In
- AK20
- JESD1/AIF1_RXN_SOC
- Sw Out
- JESD1_RXN_FMC1
  or AIF1_RXN_AMC
- -
- JESD1_RXN_FMC1
- A3
- TXN_S2
- AIF1_RXN_AMC
- 147
- CSISC2_0_RXP1
- Diff In
- AK19
- JESD1/AIF1_RXP_SOC
- Sw Out
- JESD1_RXP_FMC1
  or AIF1_RXP_AMC
- -
- JESD1_RXP_FMC1
- A2
- TXP_S2
- AIF1_RXP_AMC
- 148
- CSISC2_0_TXN0
- Diff Out
- AH17
- JESD0/AIF0_TXN_SOC
- Sw In
- JESD0_TXN_FMC1
  or AIF0_TXN_AMC
- JESD0_TXN_FMC1
- C3
- NU
- C3
- RXN_S1
- AIF0_TXN_AMC
- 144
- CSISC2_0_TXP0
- Diff Out
- AH18
- JESD0/AIF0_TXP_SOC
- Sw In
- JESD0_TXP_FMC1
  or AIF0_TXP_AMC
- JESD0_TXP_FMC1
- C2
- NU
- C2
- RXP_S1
- AIF0_TXP_AMC
- 145
- CSISC2_0_TXN1
- Diff Out
- AG18
- JESD1/AIF1_TXN_SOC
- Sw In
- JESD1_TXN_FMC1
  or AIF1_TXN_AMC
- JESD1_TXN_FMC1
- A27
- NU
- A27
- RXN_S2
- AIF1_TXN_AMC
- 150
- CSISC2_0_TXP1
- Diff Out
- AG19
- JESD1/AIF1_TXP_SOC
- Sw In
- JESD1_TXP_FMC1
  or AIF1_TXP_AMC
- JESD1_TXP_FMC1
- A26
- NU
- A26
- RXP_S2
- AIF1_TXP_AMC
- 151
sheet 46
- FMC Interface to JESD/RF devices - 2
